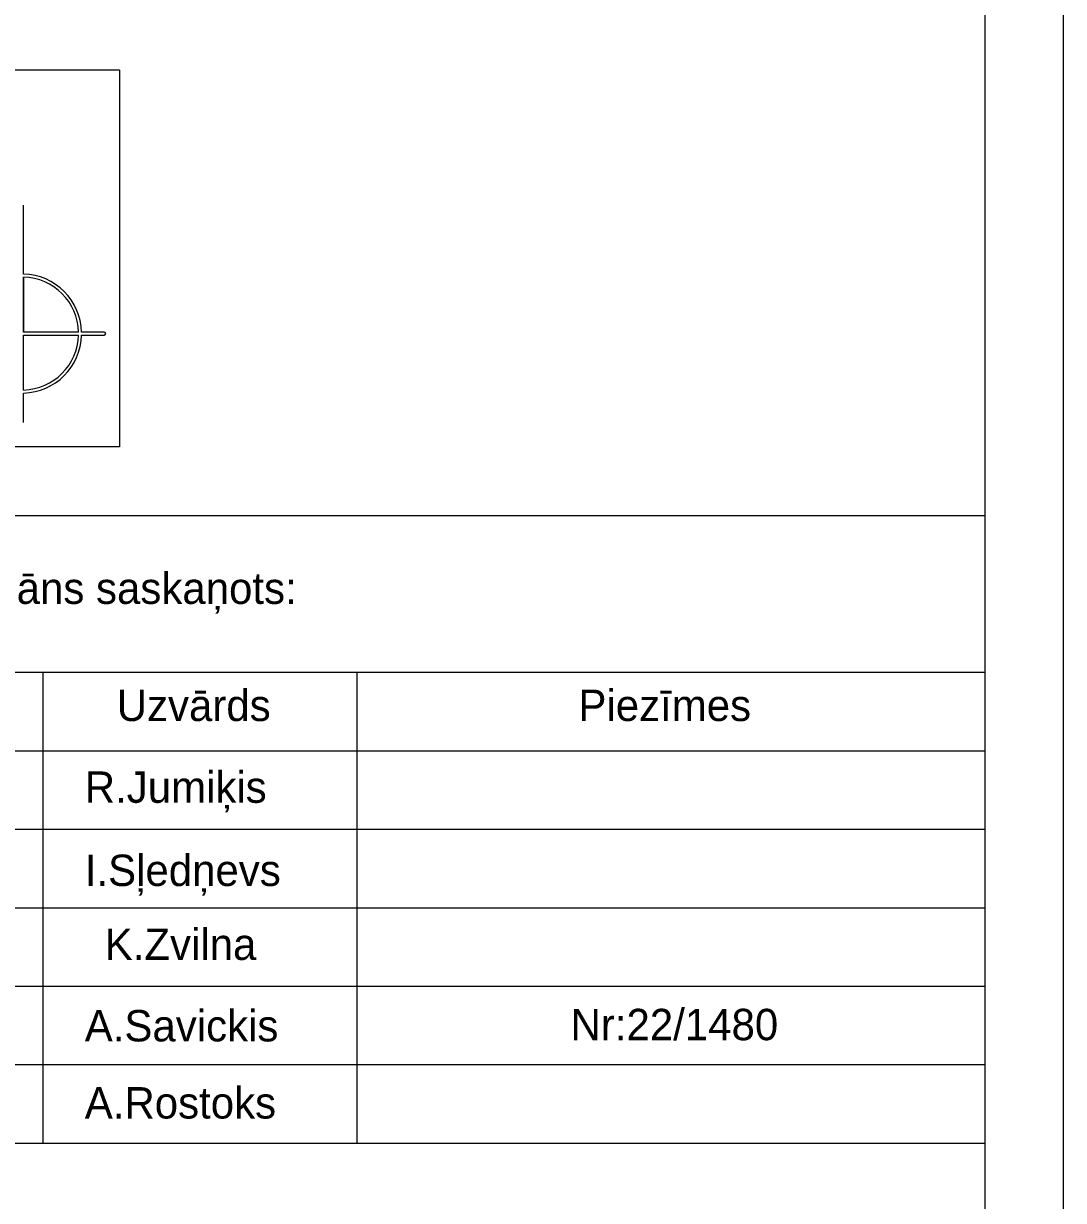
# Model space of a CAD drawing. Extents: x 532933 to 533143, y 328014 to 328163.
# Drawn here: x 533109.97 to 533143.1, y 328057.44 to 328094.94 of the extents above; entities that cross this region are included whole.
import ezdxf

# ---------------------------------------------------------------- set-up
doc = ezdxf.new("R2010")
doc.units = 0
doc.layers.add('RAMI_PLAN_####_TKST_#', color=7, linetype='Continuous')

msp = doc.modelspace()

# ---------------------------------------------------------------- linework, layer by layer
at = {"layer": 'RAMI_PLAN_####_TKST_#'}
for p, q in [((533143.097, 328014.273), (533143.097, 328162.773)), ((533140.597, 328160.273), (533140.597, 328016.773)), ((533113.028, 328093.459), (533063.028, 328093.459)), ((533113.028, 328093.459), (533113.028, 328081.459)), ((533109.971, 328086.963), (533109.971, 328089.154)), ((533109.971, 328086.866), (533109.971, 328085.115)), ((533109.971, 328085.115), (533109.971, 328086.866)), ((533109.971, 328085.115), (533109.971, 328086.866)), ((533111.721, 328085.115), (533109.971, 328085.115)), ((533109.971, 328085.018), (533111.721, 328085.018)), ((533109.971, 328083.267), (533109.971, 328085.018)), ((533112.538, 328085.115), (533111.819, 328085.115)), ((533111.819, 328085.018), (533112.538, 328085.018)), ((533109.971, 328082.234), (533109.971, 328083.17)), ((533113.028, 328081.459), (533063.028, 328081.459)), ((533140.597, 328079.273), (533140.597, 328069.273)), ((533048.097, 328059.273), (533140.597, 328059.273))]:
    msp.add_line(p, q, dxfattribs=at)
for points in [[(533140.597, 328160.273), (533140.597, 328054.273)], [(533048.097, 328079.273), (533140.597, 328079.273)], [(533048.097, 328074.273), (533140.597, 328074.273)], [(533110.597, 328059.273), (533110.597, 328074.273)], [(533120.597, 328059.273), (533120.597, 328074.273)], [(533048.097, 328071.773), (533140.597, 328071.773)], [(533048.097, 328069.273), (533140.597, 328069.273)], [(533048.097, 328066.773), (533140.597, 328066.773)], [(533048.097, 328064.273), (533140.597, 328064.273)], [(533048.097, 328061.773), (533140.597, 328061.773)], [(533048.097, 328059.273), (533140.597, 328059.273)]]:
    msp.add_lwpolyline(points, dxfattribs=at)
for centre, radius, start, end in [((533109.922, 328085.067), 1.897, 1.4722, 88.5278), ((533109.922, 328085.067), 1.8, 1.552, 88.448), ((533109.922, 328085.067), 1.897, 271.4722, 358.5278), ((533109.922, 328085.067), 1.8, 271.552, 358.448), ((533112.538, 328085.067), 0.0487, 270, 90)]:
    msp.add_arc(centre, radius, start, end, dxfattribs=at)

# ---------------------------------------------------------------- texts
for s, p in [('Sertificēts mērnieks Ģirts Pētersons apliecina, ka topogrāfiskais plāns saskaņots:', (533070.659, 328076.452)), ('Uzvārds', (533112.939, 328072.72)), ('Piezīmes', (533127.647, 328072.72)), ('R.Jumiķis', (533111.921, 328070.115)), ('I.Sļedņevs', (533111.921, 328067.464)), ('K.Zvilna', (533112.557, 328065.108)), ('A.Savickis', (533111.921, 328062.512)), ('Nr:22/1480', (533127.395, 328062.55)), ('A.Rostoks', (533111.921, 328060.055))]:
    msp.add_text(s, height=1, dxfattribs=at).set_placement(p)

doc.saveas('drawing.dxf')
